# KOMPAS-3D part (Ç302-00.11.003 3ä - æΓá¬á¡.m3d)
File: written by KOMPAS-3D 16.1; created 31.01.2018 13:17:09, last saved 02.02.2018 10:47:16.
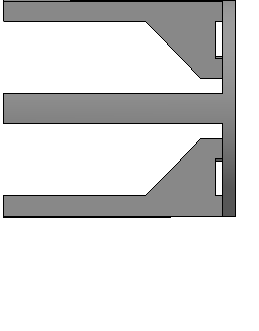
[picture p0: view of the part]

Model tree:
1. Эскиз:1
2. Операция вращения:1
     Угол 1 = 360
3. Эскиз:4
4. Операция выдавливания:3
     Расстояние 1 = 3.5; Расстояние 2 = 160
5. Эскиз:3
6. Вырезать элемент выдавливания:1
     Расстояние 1 = 58.5
7. Массив по концентрической сетке:2  (with: Вырезать элемент выдавливания:1, Эскиз:3)  (4 pattern instances)
     Геометрический массив = 3; Шаг 2 = 360
8. Эскиз:5
9. Вырезать элемент выдавливания:2
     Расстояние 1 = 2
10. Фаска:1
     Угол = 45; Длина 1 = 1; Длина 2 = 1
11. Эскиз:7
12. Сечение поверхностью:1

Expressions: v184+10; 57.50+1
Referenced files in D:\МЭ200\Макеты\: Заготовка стакан.m3d
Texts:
  Линейный размер с обрывом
